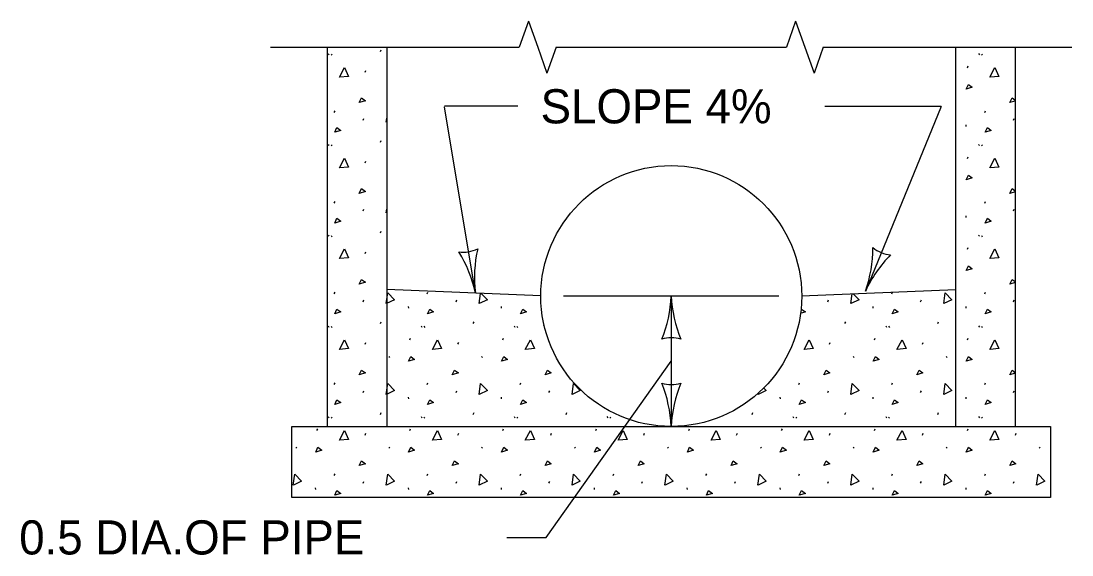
# Model space of a CAD drawing. Extents: x 49991.4 to 50028.3, y 49987.6 to 50011.4.
# Drawn here: x 50018.879 to 50020.726, y 49994.843 to 49995.781 of the extents above; entities that cross this region are included whole.
import ezdxf

# ---------------------------------------------------------------- set-up
doc = ezdxf.new("R2010")
doc.units = 0
for name, color, linetype in [('Level 1', 7, 'Continuous'), ('Level 2', 7, 'Continuous'), ('Level 3', 7, 'Continuous'), ('Level 6', 7, 'Continuous')]:
    doc.layers.add(name, color=color, linetype=linetype)

msp = doc.modelspace()

# ---------------------------------------------------------------- linework, layer by layer
at = {"layer": 'Level 1'}
for p, q in [((50019.4174, 49995.0691), (50019.4174, 49995.7358)), ((50019.5104, 49995.7281), (50019.5117, 49995.7311)), ((50019.5215, 49995.7358), (50019.5215, 49995.0691)), ((50020.5215, 49995.0691), (50020.5215, 49995.7358)), ((50020.6256, 49995.7358), (50020.6256, 49995.0691)), ((50019.4187, 49995.7242), (50019.42, 49995.7222)), ((50019.4238, 49995.7234), (50019.4251, 49995.7214)), ((50020.5616, 49995.7242), (50020.5629, 49995.7222)), ((50020.5666, 49995.7234), (50020.568, 49995.7214)), ((50019.4834, 49995.6918), (50019.4847, 49995.6948)), ((50020.5419, 49995.6995), (50020.5432, 49995.7025)), ((50019.4294, 49995.6209), (50019.4308, 49995.6239)), ((50020.5723, 49995.6209), (50020.5736, 49995.6239)), ((50019.48, 49995.6073), (50019.4814, 49995.6103)), ((50020.5388, 49995.5989), (50020.5392, 49995.5959)), ((50020.6229, 49995.6073), (50020.6242, 49995.6103)), ((50019.4187, 49995.5647), (50019.42, 49995.5627)), ((50019.4238, 49995.5639), (50019.4251, 49995.5619)), ((50019.5104, 49995.5686), (50019.5117, 49995.5716)), ((50020.5616, 49995.5647), (50020.5629, 49995.5627)), ((50020.5666, 49995.5639), (50020.568, 49995.5619)), ((50020.5419, 49995.54), (50020.5432, 49995.543)), ((50019.4834, 49995.5324), (50019.4847, 49995.5354)), ((50019.4294, 49995.4615), (50019.4308, 49995.4645)), ((50019.48, 49995.4478), (50019.4814, 49995.4508)), ((50020.5723, 49995.4615), (50020.5736, 49995.4645)), ((50020.6229, 49995.4478), (50020.6242, 49995.4508)), ((50020.5388, 49995.4394), (50020.5392, 49995.4364)), ((50019.5104, 49995.4092), (50019.5117, 49995.4121)), ((50019.4187, 49995.4053), (50019.42, 49995.4033)), ((50019.4238, 49995.4045), (50019.4251, 49995.4025)), ((50020.5616, 49995.4053), (50020.5629, 49995.4033)), ((50020.5666, 49995.4045), (50020.568, 49995.4025)), ((50019.4834, 49995.3729), (50019.4847, 49995.3759)), ((50020.5419, 49995.3806), (50020.5432, 49995.3836)), ((50019.4294, 49995.302), (50019.4308, 49995.305)), ((50019.7923, 49995.2983), (50019.5215, 49995.3096)), ((50019.5927, 49995.302), (50019.594, 49995.305)), ((50020.2506, 49995.2983), (50020.5215, 49995.3096)), ((50020.409, 49995.302), (50020.4104, 49995.3049)), ((50020.5723, 49995.302), (50020.5736, 49995.305)), ((50019.48, 49995.2883), (50019.4814, 49995.2913)), ((50019.6433, 49995.2883), (50019.6446, 49995.2913)), ((50020.2964, 49995.2883), (50020.2977, 49995.2913)), ((50020.4596, 49995.2883), (50020.461, 49995.2913)), ((50020.6229, 49995.2883), (50020.6242, 49995.2913)), ((50019.5592, 49995.28), (50019.5596, 49995.277)), ((50019.7225, 49995.28), (50019.7228, 49995.277)), ((50020.3756, 49995.28), (50020.3759, 49995.277)), ((50020.5388, 49995.28), (50020.5392, 49995.277)), ((50019.4187, 49995.2458), (50019.42, 49995.2438)), ((50019.5104, 49995.2497), (50019.5117, 49995.2527)), ((50019.582, 49995.2458), (50019.5833, 49995.2438)), ((50019.6736, 49995.2497), (50019.675, 49995.2527)), ((50019.7452, 49995.2458), (50019.7466, 49995.2438)), ((50020.3267, 49995.2497), (50020.328, 49995.2527)), ((50020.3983, 49995.2458), (50020.3996, 49995.2438)), ((50020.49, 49995.2497), (50020.4913, 49995.2527)), ((50020.5616, 49995.2458), (50020.5629, 49995.2438)), ((50019.4238, 49995.2451), (50019.4251, 49995.2431)), ((50019.587, 49995.2451), (50019.5884, 49995.2431)), ((50019.7503, 49995.2451), (50019.7516, 49995.2431)), ((50020.4034, 49995.2451), (50020.4047, 49995.2431)), ((50020.5666, 49995.2451), (50020.568, 49995.2431)), ((50019.4834, 49995.2135), (50019.4847, 49995.2165)), ((50019.5623, 49995.2211), (50019.5636, 49995.2241)), ((50019.6466, 49995.2135), (50019.648, 49995.2165)), ((50019.7256, 49995.2211), (50019.7269, 49995.2241)), ((50020.2997, 49995.2135), (50020.301, 49995.2165)), ((50020.3786, 49995.2211), (50020.38, 49995.2241)), ((50020.463, 49995.2135), (50020.4643, 49995.2165)), ((50020.5419, 49995.2211), (50020.5432, 49995.2241)), ((50019.525, 49995.1921), (50019.5264, 49995.1901)), ((50019.6883, 49995.1921), (50019.6896, 49995.1901)), ((50020.3414, 49995.1921), (50020.3427, 49995.1901)), ((50020.5046, 49995.1921), (50020.506, 49995.1901)), ((50019.4294, 49995.1425), (50019.4308, 49995.1455)), ((50019.5927, 49995.1425), (50019.594, 49995.1455)), ((50019.756, 49995.1425), (50019.7573, 49995.1455)), ((50020.2458, 49995.1425), (50020.2471, 49995.1455)), ((50020.409, 49995.1425), (50020.4104, 49995.1455)), ((50020.5723, 49995.1425), (50020.5736, 49995.1455)), ((50019.48, 49995.1289), (50019.4814, 49995.1319)), ((50019.5592, 49995.1205), (50019.5596, 49995.1175)), ((50019.6433, 49995.1289), (50019.6446, 49995.1319)), ((50019.7225, 49995.1205), (50019.7228, 49995.1175)), ((50019.8066, 49995.1289), (50019.8079, 49995.1319)), ((50020.2123, 49995.1205), (50020.2126, 49995.1175)), ((50020.2964, 49995.1289), (50020.2977, 49995.1319)), ((50020.3756, 49995.1205), (50020.3759, 49995.1175)), ((50020.4596, 49995.1289), (50020.461, 49995.1319)), ((50020.5388, 49995.1205), (50020.5392, 49995.1175)), ((50020.6229, 49995.1289), (50020.6242, 49995.1319)), ((50019.4187, 49995.0863), (50019.42, 49995.0843)), ((50019.4238, 49995.0856), (50019.4251, 49995.0836)), ((50019.5104, 49995.0903), (50019.5117, 49995.0933)), ((50019.582, 49995.0863), (50019.5833, 49995.0843)), ((50019.587, 49995.0856), (50019.5884, 49995.0836)), ((50019.6736, 49995.0903), (50019.675, 49995.0933)), ((50019.7452, 49995.0863), (50019.7466, 49995.0843)), ((50019.7503, 49995.0856), (50019.7516, 49995.0836)), ((50019.8369, 49995.0903), (50019.8382, 49995.0933)), ((50019.9085, 49995.0863), (50019.9098, 49995.0843)), ((50019.9136, 49995.0856), (50019.9149, 49995.0836)), ((50020.1634, 49995.0903), (50020.1648, 49995.0933)), ((50020.235, 49995.0863), (50020.2364, 49995.0843)), ((50020.2401, 49995.0856), (50020.2414, 49995.0836)), ((50020.3267, 49995.0903), (50020.328, 49995.0933)), ((50020.3983, 49995.0863), (50020.3996, 49995.0843)), ((50020.4034, 49995.0856), (50020.4047, 49995.0836)), ((50020.49, 49995.0903), (50020.4913, 49995.0933)), ((50020.5616, 49995.0863), (50020.5629, 49995.0843)), ((50020.5666, 49995.0856), (50020.568, 49995.0836)), ((50019.3548, 49995.0691), (50020.6881, 49995.0691)), ((50019.3548, 49995.0691), (50020.6881, 49995.0691)), ((50019.3548, 49995.0691), (50020.6881, 49995.0691)), ((50019.3548, 49994.9441), (50019.3548, 49995.0691)), ((50019.399, 49995.0617), (50019.4004, 49995.0647)), ((50019.5623, 49995.0617), (50019.5636, 49995.0647)), ((50019.7256, 49995.0617), (50019.7269, 49995.0647)), ((50019.8888, 49995.0617), (50019.8902, 49995.0647)), ((50020.0521, 49995.0617), (50020.0534, 49995.0647)), ((50020.2154, 49995.0617), (50020.2167, 49995.0647)), ((50020.3786, 49995.0617), (50020.38, 49995.0647)), ((50020.5419, 49995.0617), (50020.5432, 49995.0647)), ((50020.6881, 49995.0691), (50020.6881, 49994.9441)), ((50019.4834, 49995.054), (50019.4847, 49995.057)), ((50019.6466, 49995.054), (50019.648, 49995.057)), ((50019.8099, 49995.054), (50019.8112, 49995.057)), ((50019.9732, 49995.054), (50019.9745, 49995.057)), ((50020.1364, 49995.054), (50020.1378, 49995.057)), ((50020.2997, 49995.054), (50020.301, 49995.057)), ((50020.463, 49995.054), (50020.4643, 49995.057)), ((50020.6262, 49995.054), (50020.6276, 49995.057)), ((50019.3618, 49995.0327), (50019.3631, 49995.0307)), ((50019.525, 49995.0327), (50019.5264, 49995.0307)), ((50019.6883, 49995.0327), (50019.6896, 49995.0307)), ((50019.8516, 49995.0327), (50019.8529, 49995.0307)), ((50020.0148, 49995.0327), (50020.0162, 49995.0307)), ((50020.1781, 49995.0327), (50020.1794, 49995.0307)), ((50020.3414, 49995.0327), (50020.3427, 49995.0307)), ((50020.5046, 49995.0327), (50020.506, 49995.0307)), ((50020.6679, 49995.0327), (50020.6692, 49995.0307)), ((50019.4294, 49994.9831), (50019.4308, 49994.9861)), ((50019.48, 49994.9694), (50019.4814, 49994.9724)), ((50019.5927, 49994.9831), (50019.594, 49994.9861)), ((50019.6433, 49994.9694), (50019.6446, 49994.9724)), ((50019.756, 49994.9831), (50019.7573, 49994.9861)), ((50019.8066, 49994.9694), (50019.8079, 49994.9724)), ((50019.9192, 49994.9831), (50019.9206, 49994.9861)), ((50019.9698, 49994.9694), (50019.9712, 49994.9724)), ((50020.0825, 49994.9831), (50020.0838, 49994.9861)), ((50020.1331, 49994.9694), (50020.1344, 49994.9724)), ((50020.2458, 49994.9831), (50020.2471, 49994.9861)), ((50020.2964, 49994.9694), (50020.2977, 49994.9724)), ((50020.409, 49994.9831), (50020.4104, 49994.9861)), ((50020.4596, 49994.9694), (50020.461, 49994.9724)), ((50020.5723, 49994.9831), (50020.5736, 49994.9861)), ((50020.6229, 49994.9694), (50020.6242, 49994.9724)), ((50019.396, 49994.9611), (50019.3963, 49994.9581)), ((50019.5592, 49994.9611), (50019.5596, 49994.9581)), ((50019.7225, 49994.9611), (50019.7228, 49994.9581)), ((50019.8858, 49994.9611), (50019.8861, 49994.9581)), ((50020.049, 49994.9611), (50020.0494, 49994.9581)), ((50020.2123, 49994.9611), (50020.2126, 49994.9581)), ((50020.3756, 49994.9611), (50020.3759, 49994.9581)), ((50020.5388, 49994.9611), (50020.5392, 49994.9581)), ((50020.6881, 49994.9441), (50019.3548, 49994.9441))]:
    msp.add_line(p, q, dxfattribs=at)
for points in [[(50019.4384, 49995.6829), (50019.4474, 49995.6998), (50019.4544, 49995.6842), (50019.4388, 49995.6829)], [(50020.5813, 49995.6829), (50020.5903, 49995.6998), (50020.5973, 49995.6842), (50020.5816, 49995.6829)], [(50020.5396, 49995.6619), (50020.5436, 49995.6702), (50020.5502, 49995.6652), (50020.5396, 49995.6619)], [(50019.4734, 49995.6381), (50019.4774, 49995.6464), (50019.4841, 49995.6414), (50019.4734, 49995.6381)], [(50020.6163, 49995.6381), (50020.6203, 49995.6464), (50020.6256, 49995.6424)], [(50020.6256, 49995.6409), (50020.6163, 49995.6381)], [(50019.5206, 49995.6038), (50019.5215, 49995.6105)], [(50019.5215, 49995.6042), (50019.5209, 49995.6039)], [(50019.4301, 49995.5859), (50019.4341, 49995.5943), (50019.4408, 49995.5893), (50019.4301, 49995.5859)], [(50020.573, 49995.5859), (50020.577, 49995.5943), (50020.5836, 49995.5893), (50020.573, 49995.5859)], [(50019.4384, 49995.5234), (50019.4474, 49995.5404), (50019.4544, 49995.5247), (50019.4388, 49995.5234)], [(50020.5813, 49995.5234), (50020.5903, 49995.5404), (50020.5973, 49995.5247), (50020.5816, 49995.5234)], [(50020.5396, 49995.5024), (50020.5436, 49995.5107), (50020.5502, 49995.5057), (50020.5396, 49995.5024)], [(50019.4734, 49995.4786), (50019.4774, 49995.4869), (50019.4841, 49995.4819), (50019.4734, 49995.4786)], [(50020.6163, 49995.4786), (50020.6203, 49995.4869), (50020.6256, 49995.4829)], [(50020.6256, 49995.4815), (50020.6163, 49995.4786)], [(50019.5206, 49995.4443), (50019.5215, 49995.4511)], [(50019.4301, 49995.4265), (50019.4341, 49995.4348), (50019.4408, 49995.4298), (50019.4301, 49995.4265)], [(50019.5215, 49995.4447), (50019.5209, 49995.4445)], [(50020.573, 49995.4265), (50020.577, 49995.4348), (50020.5836, 49995.4298), (50020.573, 49995.4265)], [(50019.4384, 49995.3639), (50019.4474, 49995.3809), (50019.4544, 49995.3653), (50019.4388, 49995.3639)], [(50020.5813, 49995.3639), (50020.5903, 49995.3809), (50020.5973, 49995.3653), (50020.5816, 49995.3639)], [(50020.5396, 49995.3429), (50020.5436, 49995.3513), (50020.5502, 49995.3463), (50020.5396, 49995.3429)], [(50019.4734, 49995.3191), (50019.4774, 49995.3275), (50019.4841, 49995.3225), (50019.4734, 49995.3191)], [(50020.6163, 49995.3191), (50020.6203, 49995.3275), (50020.6256, 49995.3235)], [(50020.6256, 49995.3221), (50020.6163, 49995.3191)], [(50019.5206, 49995.2849), (50019.5232, 49995.3039), (50019.5351, 49995.2916), (50019.5209, 49995.285)], [(50019.6838, 49995.2849), (50019.6863, 49995.3027)], [(50019.6877, 49995.3027), (50019.6984, 49995.2916), (50019.6842, 49995.285)], [(50020.3369, 49995.2849), (50020.3392, 49995.302)], [(50020.3413, 49995.3021), (50020.3514, 49995.2916), (50020.3372, 49995.285)], [(50020.5002, 49995.2849), (50020.5028, 49995.3039), (50020.5147, 49995.2916), (50020.5005, 49995.285)], [(50019.4301, 49995.267), (50019.4341, 49995.2753), (50019.4408, 49995.2703), (50019.4301, 49995.267)], [(50019.5934, 49995.267), (50019.5974, 49995.2753), (50019.604, 49995.2703), (50019.5934, 49995.267)], [(50019.7566, 49995.267), (50019.7606, 49995.2753), (50019.7673, 49995.2703), (50019.7566, 49995.267)], [(50020.2505, 49995.2753), (50020.2571, 49995.2703), (50020.2505, 49995.2683)], [(50020.4097, 49995.267), (50020.4137, 49995.2753), (50020.4204, 49995.2703), (50020.4097, 49995.267)], [(50020.573, 49995.267), (50020.577, 49995.2753), (50020.5836, 49995.2703), (50020.573, 49995.267)], [(50019.7975, 49995.2465), (50019.7976, 49995.2468)], [(50019.7977, 49995.2465), (50019.7975, 49995.2465)], [(50019.4384, 49995.2045), (50019.4474, 49995.2215), (50019.4544, 49995.2058), (50019.4388, 49995.2045)], [(50019.6017, 49995.2045), (50019.6107, 49995.2215), (50019.6177, 49995.2058), (50019.602, 49995.2045)], [(50019.765, 49995.2045), (50019.774, 49995.2215), (50019.781, 49995.2058), (50019.7653, 49995.2045)], [(50020.2548, 49995.2045), (50020.2638, 49995.2215), (50020.2708, 49995.2058), (50020.2551, 49995.2045)], [(50020.418, 49995.2045), (50020.427, 49995.2215), (50020.434, 49995.2058), (50020.4184, 49995.2045)], [(50020.5813, 49995.2045), (50020.5903, 49995.2215), (50020.5973, 49995.2058), (50020.5816, 49995.2045)], [(50019.56, 49995.1835), (50019.564, 49995.1918), (50019.5706, 49995.1868), (50019.56, 49995.1835)], [(50019.7232, 49995.1835), (50019.7272, 49995.1918), (50019.7339, 49995.1868), (50019.7232, 49995.1835)], [(50020.3763, 49995.1835), (50020.3803, 49995.1918), (50020.387, 49995.1868), (50020.3763, 49995.1835)], [(50020.5396, 49995.1835), (50020.5436, 49995.1918), (50020.5502, 49995.1868), (50020.5396, 49995.1835)], [(50019.4734, 49995.1597), (50019.4774, 49995.168), (50019.4841, 49995.163), (50019.4734, 49995.1597)], [(50019.6367, 49995.1597), (50019.6407, 49995.168), (50019.6474, 49995.163), (50019.6367, 49995.1597)], [(50019.8, 49995.1597), (50019.804, 49995.168), (50019.8106, 49995.163), (50019.8, 49995.1597)], [(50020.2898, 49995.1597), (50020.2938, 49995.168), (50020.3004, 49995.163), (50020.2898, 49995.1597)], [(50020.453, 49995.1597), (50020.457, 49995.168), (50020.4637, 49995.163), (50020.453, 49995.1597)], [(50020.6163, 49995.1597), (50020.6203, 49995.168), (50020.6256, 49995.1641)], [(50020.6256, 49995.1626), (50020.6163, 49995.1597)], [(50019.5206, 49995.1254), (50019.5232, 49995.1445), (50019.5351, 49995.1321), (50019.5209, 49995.1255)], [(50019.6838, 49995.1254), (50019.6865, 49995.1445), (50019.6984, 49995.1321), (50019.6842, 49995.1255)], [(50019.8471, 49995.1254), (50019.8498, 49995.1445), (50019.8617, 49995.1321), (50019.8474, 49995.1255)], [(50020.1839, 49995.1366), (50020.1882, 49995.1321), (50020.174, 49995.1255)], [(50020.3369, 49995.1254), (50020.3395, 49995.1445), (50020.3514, 49995.1321), (50020.3372, 49995.1255)], [(50020.5002, 49995.1254), (50020.5028, 49995.1445), (50020.5147, 49995.1321), (50020.5005, 49995.1255)], [(50020.1736, 49995.1254), (50020.1738, 49995.1263)], [(50019.4301, 49995.1076), (50019.4341, 49995.1159), (50019.4408, 49995.1109), (50019.4301, 49995.1076)], [(50019.5934, 49995.1076), (50019.5974, 49995.1159), (50019.604, 49995.1109), (50019.5934, 49995.1076)], [(50019.7566, 49995.1076), (50019.7606, 49995.1159), (50019.7673, 49995.1109), (50019.7566, 49995.1076)], [(50020.2464, 49995.1076), (50020.2504, 49995.1159), (50020.2571, 49995.1109), (50020.2464, 49995.1076)], [(50020.4097, 49995.1076), (50020.4137, 49995.1159), (50020.4204, 49995.1109), (50020.4097, 49995.1076)], [(50020.573, 49995.1076), (50020.577, 49995.1159), (50020.5836, 49995.1109), (50020.573, 49995.1076)], [(50019.4384, 49995.045), (50019.4474, 49995.062), (50019.4544, 49995.0463), (50019.4388, 49995.045)], [(50019.6017, 49995.045), (50019.6107, 49995.062), (50019.6177, 49995.0463), (50019.602, 49995.045)], [(50019.765, 49995.045), (50019.774, 49995.062), (50019.781, 49995.0463), (50019.7653, 49995.045)], [(50019.9282, 49995.045), (50019.9372, 49995.062), (50019.9442, 49995.0463), (50019.9286, 49995.045)], [(50020.0915, 49995.045), (50020.1005, 49995.062), (50020.1075, 49995.0463), (50020.0918, 49995.045)], [(50020.2548, 49995.045), (50020.2638, 49995.062), (50020.2708, 49995.0463), (50020.2551, 49995.045)], [(50020.418, 49995.045), (50020.427, 49995.062), (50020.434, 49995.0463), (50020.4184, 49995.045)], [(50020.5813, 49995.045), (50020.5903, 49995.062), (50020.5973, 49995.0463), (50020.5816, 49995.045)], [(50019.3967, 49995.0241), (50019.4007, 49995.0324), (50019.4074, 49995.0274), (50019.3967, 49995.0241)], [(50019.56, 49995.0241), (50019.564, 49995.0324), (50019.5706, 49995.0274), (50019.56, 49995.0241)], [(50019.7232, 49995.0241), (50019.7272, 49995.0324), (50019.7339, 49995.0274), (50019.7232, 49995.0241)], [(50019.8865, 49995.0241), (50019.8905, 49995.0324), (50019.8972, 49995.0274), (50019.8865, 49995.0241)], [(50020.0498, 49995.0241), (50020.0538, 49995.0324), (50020.0604, 49995.0274), (50020.0498, 49995.0241)], [(50020.213, 49995.0241), (50020.217, 49995.0324), (50020.2237, 49995.0274), (50020.213, 49995.0241)], [(50020.3763, 49995.0241), (50020.3803, 49995.0324), (50020.387, 49995.0274), (50020.3763, 49995.0241)], [(50020.5396, 49995.0241), (50020.5436, 49995.0324), (50020.5502, 49995.0274), (50020.5396, 49995.0241)], [(50019.4734, 49995.0002), (50019.4774, 49995.0085), (50019.4841, 49995.0036), (50019.4734, 49995.0002)], [(50019.6367, 49995.0002), (50019.6407, 49995.0085), (50019.6474, 49995.0036), (50019.6367, 49995.0002)], [(50019.8, 49995.0002), (50019.804, 49995.0085), (50019.8106, 49995.0036), (50019.8, 49995.0002)], [(50019.9632, 49995.0002), (50019.9672, 49995.0085), (50019.9739, 49995.0036), (50019.9632, 49995.0002)], [(50020.1265, 49995.0002), (50020.1305, 49995.0085), (50020.1372, 49995.0036), (50020.1265, 49995.0002)], [(50020.2898, 49995.0002), (50020.2938, 49995.0085), (50020.3004, 49995.0036), (50020.2898, 49995.0002)], [(50020.453, 49995.0002), (50020.457, 49995.0085), (50020.4637, 49995.0036), (50020.453, 49995.0002)], [(50020.6163, 49995.0002), (50020.6203, 49995.0085), (50020.627, 49995.0036), (50020.6163, 49995.0002)], [(50019.3573, 49994.966), (50019.36, 49994.985), (50019.3719, 49994.9727), (50019.3576, 49994.9661)], [(50019.5206, 49994.966), (50019.5232, 49994.985), (50019.5351, 49994.9727), (50019.5209, 49994.9661)], [(50019.6838, 49994.966), (50019.6865, 49994.985), (50019.6984, 49994.9727), (50019.6842, 49994.9661)], [(50019.8471, 49994.966), (50019.8498, 49994.985), (50019.8617, 49994.9727), (50019.8474, 49994.9661)], [(50020.0104, 49994.966), (50020.013, 49994.985), (50020.0249, 49994.9727), (50020.0107, 49994.9661)], [(50020.1736, 49994.966), (50020.1763, 49994.985), (50020.1882, 49994.9727), (50020.174, 49994.9661)], [(50020.3369, 49994.966), (50020.3395, 49994.985), (50020.3514, 49994.9727), (50020.3372, 49994.9661)], [(50020.5002, 49994.966), (50020.5028, 49994.985), (50020.5147, 49994.9727), (50020.5005, 49994.9661)], [(50020.6634, 49994.966), (50020.6661, 49994.985), (50020.678, 49994.9727), (50020.6638, 49994.9661)], [(50019.4301, 49994.9481), (50019.4341, 49994.9565), (50019.4408, 49994.9515), (50019.4301, 49994.9481)], [(50019.5934, 49994.9481), (50019.5974, 49994.9565), (50019.604, 49994.9515), (50019.5934, 49994.9481)], [(50019.7566, 49994.9481), (50019.7606, 49994.9565), (50019.7673, 49994.9515), (50019.7566, 49994.9481)], [(50019.9199, 49994.9481), (50019.9239, 49994.9565), (50019.9306, 49994.9515), (50019.9199, 49994.9481)], [(50020.0832, 49994.9481), (50020.0872, 49994.9565), (50020.0938, 49994.9515), (50020.0832, 49994.9481)], [(50020.2464, 49994.9481), (50020.2504, 49994.9565), (50020.2571, 49994.9515), (50020.2464, 49994.9481)], [(50020.4097, 49994.9481), (50020.4137, 49994.9565), (50020.4204, 49994.9515), (50020.4097, 49994.9481)], [(50020.573, 49994.9481), (50020.577, 49994.9565), (50020.5836, 49994.9515), (50020.573, 49994.9481)], [(50020.679, 49994.9443), (50020.6789, 49994.9441)]]:
    msp.add_lwpolyline(points, dxfattribs=at)
msp.add_ellipse((50020.0215, 49995.2982), major_axis=(0, 0.2292), ratio=0.99996, dxfattribs=at)
at = {"layer": 'Level 3'}
for p, q in [((50019.7519, 49995.6316), (50019.6233, 49995.6316)), ((50019.6776, 49995.3034), (50019.6233, 49995.6307)), ((50020.2912, 49995.6316), (50020.4959, 49995.6316)), ((50020.4959, 49995.6315), (50020.3628, 49995.3063)), ((50019.8323, 49995.2983), (50020.2106, 49995.2983)), ((50020.0215, 49995.2983), (50020.0215, 49995.0691))]:
    msp.add_line(p, q, dxfattribs=at)
msp.add_lwpolyline([(50019.7327, 49994.8741), (50019.8014, 49994.8741), (50020.0215, 49995.1837)], dxfattribs=at)
for centre, radius, start, end in [((50019.6563, 49995.43), 0.0548, 261.5504, 297.2728), ((50019.4496, 49995.2541), 0.233, 12.2389, 31.4887), ((50019.8979, 49995.3308), 0.2223, 166.8676, 187.0511), ((50020.1429, 49995.3841), 0.233, 340.5725, 359.8223), ((50020.4112, 49995.4252), 0.0548, 229.884, 265.6064), ((50020.5647, 49995.214), 0.2223, 135.2012, 155.3847), ((50019.7994, 49995.3074), 0.2223, 337.456, 357.6395), ((50020.2542, 49995.3098), 0.233, 182.8273, 202.0772), ((50020.0215, 49995.1701), 0.0548, 72.1388, 107.8612), ((50020.0215, 49995.1973), 0.0548, 252.1388, 287.8612), ((50019.7888, 49995.0576), 0.233, 2.8273, 22.0772), ((50020.2436, 49995.0599), 0.2223, 157.456, 177.6395)]:
    msp.add_arc(centre, radius, start, end, dxfattribs=at)
at = {"layer": 'Level 6'}
for p, q in [((50019.7706, 49995.7815), (50019.7544, 49995.7358)), ((50019.7706, 49995.7815), (50019.7868, 49995.7358)), ((50020.24, 49995.7815), (50020.2238, 49995.7358)), ((50020.24, 49995.7815), (50020.2562, 49995.7358)), ((50019.3174, 49995.7358), (50019.7544, 49995.7358)), ((50019.7868, 49995.7358), (50019.803, 49995.6901)), ((50019.8192, 49995.7358), (50019.803, 49995.6901)), ((50019.8192, 49995.7358), (50020.2238, 49995.7358)), ((50020.2562, 49995.7358), (50020.2724, 49995.6901)), ((50020.2886, 49995.7358), (50020.2724, 49995.6901)), ((50020.2886, 49995.7358), (50020.7256, 49995.7358))]:
    msp.add_line(p, q, dxfattribs=at)

# ---------------------------------------------------------------- texts
at = {"layer": 'Level 2'}
for s, p in [('SLOPE 4%', (50019.7919, 49995.6016)), ('0.5 DIA.OF PIPE', (50018.8758, 49994.8441))]:
    msp.add_text(s, height=0.06, dxfattribs=at).set_placement(p)

doc.saveas('drawing.dxf')
